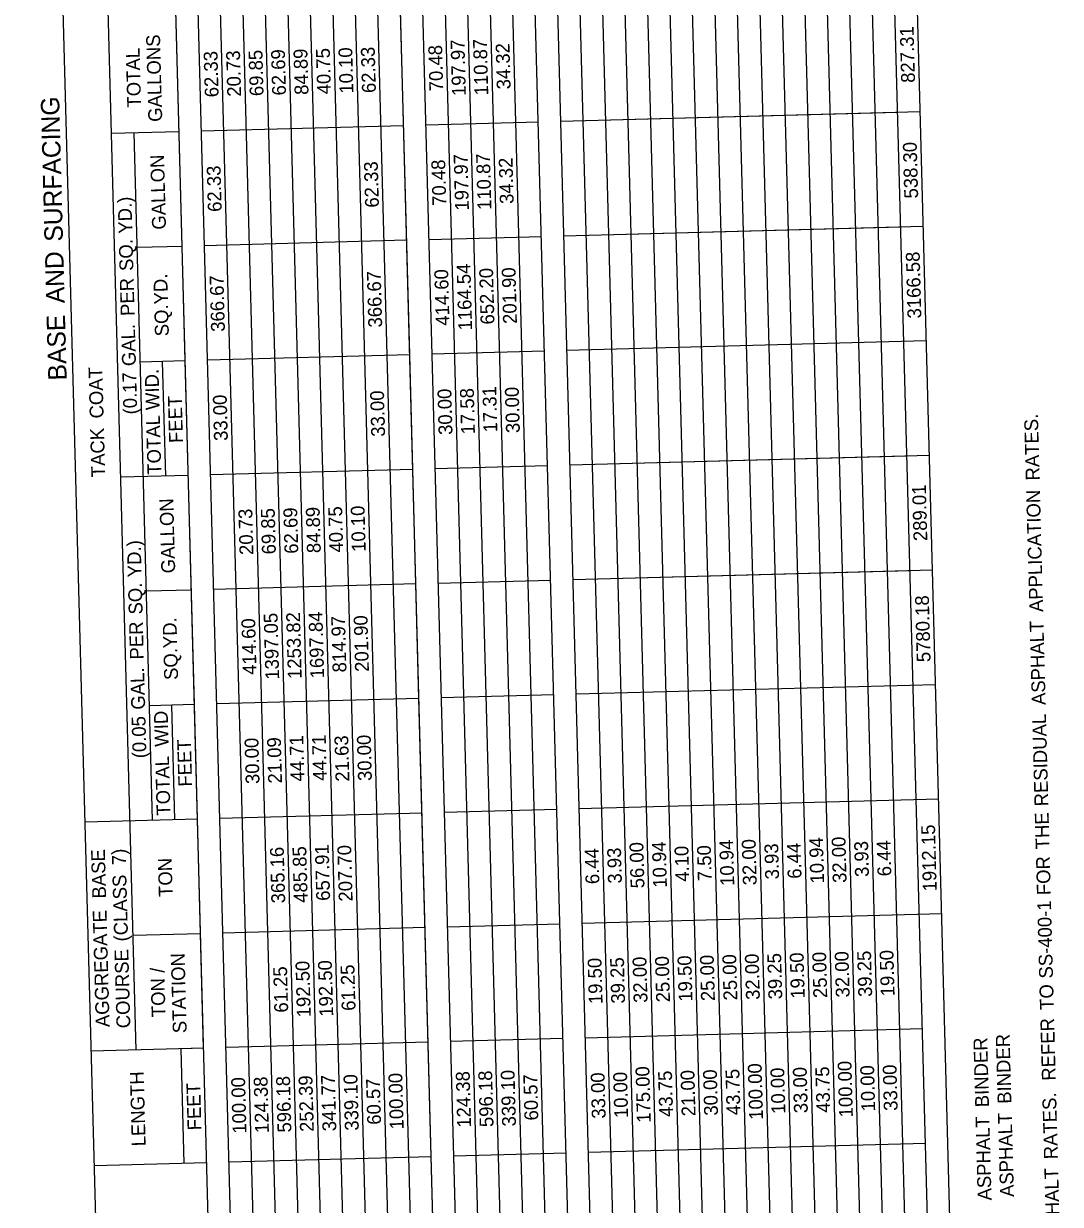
# Model space of a CAD drawing. Extents: x 1930093 to 1931323, y 596452 to 607874.
# Drawn here: x 1930485 to 1930935, y 604236 to 604748 of the extents above; entities that cross this region are included whole.
import ezdxf

# ---------------------------------------------------------------- set-up
doc = ezdxf.new("R2010")
doc.units = 0
doc.layers.add('Default', color=7, linetype='Continuous')

msp = doc.modelspace()

# ---------------------------------------------------------------- linework, layer by layer
at = {"layer": 'Default'}
for p, q in [((1930826.82, 603925.41), (1930787.13, 605403.95)), ((1930836.57, 603925.67), (1930796.88, 605404.22)), ((1930846.32, 603925.93), (1930806.63, 605404.48)), ((1930856.06, 603926.2), (1930816.37, 605404.74)), ((1930865.81, 603926.46), (1930826.12, 605405)), ((1930875.55, 603926.72), (1930835.86, 605405.26)), ((1930885.3, 603926.98), (1930845.61, 605405.52)), ((1930895.05, 603927.24), (1930855.36, 605405.79)), ((1930641.64, 603920.44), (1930601.95, 605398.98)), ((1930651.39, 603920.7), (1930611.7, 605399.24)), ((1930661.13, 603920.96), (1930621.44, 605399.51)), ((1930670.88, 603921.23), (1930631.19, 605399.77)), ((1930680.63, 603921.49), (1930640.93, 605400.03)), ((1930690.37, 603921.75), (1930650.68, 605400.29)), ((1930700.12, 603922.01), (1930660.43, 605400.55)), ((1930709.86, 603922.27), (1930670.17, 605400.81)), ((1930719.61, 603922.53), (1930679.92, 605401.08)), ((1930729.36, 603922.8), (1930689.67, 605401.34)), ((1930729.36, 603922.8), (1930689.67, 605401.34)), ((1930739.1, 603923.06), (1930699.41, 605401.6)), ((1930748.85, 603923.32), (1930709.16, 605401.86)), ((1930758.6, 603923.58), (1930718.91, 605402.12)), ((1930768.34, 603923.84), (1930728.65, 605402.38)), ((1930778.09, 603924.1), (1930738.4, 605402.65)), ((1930787.84, 603924.37), (1930748.15, 605402.91)), ((1930797.58, 603924.63), (1930757.89, 605403.17)), ((1930807.33, 603924.89), (1930767.64, 605403.43)), ((1930817.08, 603925.15), (1930777.39, 605403.69)), ((1930524.68, 603917.3), (1930484.99, 605395.84)), ((1930533.84, 604302.81), (1930504.48, 605396.37)), ((1930573.41, 603918.61), (1930533.72, 605397.15)), ((1930583.16, 603918.87), (1930543.47, 605397.41)), ((1930592.91, 603919.13), (1930553.22, 605397.67)), ((1930602.65, 603919.39), (1930562.96, 605397.94)), ((1930612.4, 603919.66), (1930572.71, 605398.2)), ((1930622.15, 603919.92), (1930582.46, 605398.46)), ((1930631.89, 603920.18), (1930592.2, 605398.72)), ((1930553.74, 604651.54), (1930549.74, 604800.67)), ((1930652.54, 604604.45), (1930648.53, 604753.58)), ((1930874.04, 604709.89), (1930718.09, 604705.7)), ((1930864.29, 604709.62), (1930718.09, 604705.7)), ((1930649.87, 604703.87), (1930562.15, 604701.51)), ((1930649.87, 604703.87), (1930562.15, 604701.51)), ((1930708.35, 604705.44), (1930659.62, 604704.13)), ((1930708.35, 604705.44), (1930659.62, 604704.13)), ((1930552.4, 604701.25), (1930523.16, 604700.47)), ((1930540.92, 604402.49), (1930532.91, 604700.73)), ((1930875.37, 604660.18), (1930719.43, 604655.99)), ((1930865.63, 604659.92), (1930719.43, 604655.99)), ((1930553.74, 604651.54), (1930534.25, 604651.02)), ((1930555.07, 604601.84), (1930553.74, 604651.54)), ((1930651.2, 604654.16), (1930563.49, 604651.81)), ((1930651.2, 604654.16), (1930563.49, 604651.81)), ((1930709.68, 604655.73), (1930660.95, 604654.42)), ((1930709.68, 604655.73), (1930660.95, 604654.42)), ((1930876.71, 604610.47), (1930720.76, 604606.29)), ((1930876.71, 604610.47), (1930720.76, 604606.29)), ((1930711.02, 604606.02), (1930662.28, 604604.72)), ((1930711.02, 604606.02), (1930662.28, 604604.72)), ((1930555.07, 604601.84), (1930535.58, 604601.31)), ((1930555.07, 604601.84), (1930545.33, 604601.58)), ((1930546.66, 604551.87), (1930545.33, 604601.58)), ((1930559.08, 604452.72), (1930555.07, 604601.84)), ((1930652.54, 604604.45), (1930564.82, 604602.1)), ((1930652.54, 604604.45), (1930564.82, 604602.1)), ((1930653.87, 604554.75), (1930652.54, 604604.45)), ((1930878.04, 604560.76), (1930722.1, 604556.58)), ((1930868.3, 604560.5), (1930722.1, 604556.58)), ((1930653.87, 604554.75), (1930566.15, 604552.39)), ((1930653.87, 604554.75), (1930566.15, 604552.39)), ((1930656.54, 604455.33), (1930653.87, 604554.75)), ((1930712.35, 604556.32), (1930663.62, 604555.01)), ((1930712.35, 604556.32), (1930663.62, 604555.01)), ((1930556.41, 604552.13), (1930527.17, 604551.35)), ((1930879.38, 604511.06), (1930723.43, 604506.87)), ((1930869.63, 604510.8), (1930723.43, 604506.87)), ((1930557.74, 604502.42), (1930538.25, 604501.9)), ((1930655.21, 604505.04), (1930567.49, 604502.69)), ((1930655.21, 604505.04), (1930567.49, 604502.69)), ((1930713.69, 604506.61), (1930664.95, 604505.3)), ((1930713.69, 604506.61), (1930664.95, 604505.3)), ((1930880.71, 604461.35), (1930724.77, 604457.16)), ((1930880.71, 604461.35), (1930724.77, 604457.16)), ((1930715.02, 604456.9), (1930666.29, 604455.59)), ((1930715.02, 604456.9), (1930666.29, 604455.59)), ((1930559.08, 604452.72), (1930539.58, 604452.19)), ((1930559.08, 604452.72), (1930549.33, 604452.45)), ((1930550.66, 604402.75), (1930549.33, 604452.45)), ((1930563.08, 604303.6), (1930559.08, 604452.72)), ((1930656.54, 604455.33), (1930568.82, 604452.98)), ((1930656.54, 604455.33), (1930568.82, 604452.98)), ((1930670.88, 603921.23), (1930656.54, 604455.33)), ((1930882.04, 604411.64), (1930726.1, 604407.46)), ((1930882.04, 604411.64), (1930726.1, 604407.46)), ((1930657.88, 604405.63), (1930570.16, 604403.27)), ((1930657.88, 604405.63), (1930570.16, 604403.27)), ((1930716.35, 604407.2), (1930667.62, 604405.89)), ((1930716.35, 604407.2), (1930667.62, 604405.89)), ((1930560.41, 604403.01), (1930511.68, 604401.7)), ((1930883.38, 604361.94), (1930727.44, 604357.75)), ((1930883.38, 604361.94), (1930727.44, 604357.75)), ((1930659.21, 604355.92), (1930571.49, 604353.56)), ((1930659.21, 604355.92), (1930571.49, 604353.56)), ((1930717.69, 604357.49), (1930668.96, 604356.18)), ((1930717.69, 604357.49), (1930668.96, 604356.18)), ((1930561.74, 604353.3), (1930532.51, 604352.52)), ((1930719.02, 604307.78), (1930670.29, 604306.47)), ((1930719.02, 604307.78), (1930670.29, 604306.47)), ((1930874.97, 604311.97), (1930728.77, 604308.04)), ((1930874.97, 604311.97), (1930728.77, 604308.04)), ((1930563.08, 604303.6), (1930514.35, 604302.29)), ((1930563.08, 604303.6), (1930553.33, 604303.33)), ((1930554.67, 604253.63), (1930553.33, 604303.33)), ((1930660.54, 604306.21), (1930572.83, 604303.86)), ((1930660.54, 604306.21), (1930572.83, 604303.86)), ((1930876.3, 604262.26), (1930730.1, 604258.34)), ((1930876.3, 604262.26), (1930730.1, 604258.34)), ((1930661.88, 604256.5), (1930574.16, 604254.15)), ((1930661.88, 604256.5), (1930574.16, 604254.15)), ((1930720.36, 604258.07), (1930671.62, 604256.77)), ((1930720.36, 604258.07), (1930671.62, 604256.77)), ((1930677.96, 604020.9), (1930671.62, 604256.77)), ((1930564.41, 604253.89), (1930515.68, 604252.58))]:
    msp.add_line(p, q, dxfattribs=at)

# ---------------------------------------------------------------- texts
for s, height, p in [('GALLONS', 6, (1930545.16, 604705.63)), ('827.31', 6, (1930871.82, 604722.56)), ('70.48', 6, (1930667.1, 604718.9)), ('197.97', 6, (1930676.91, 604716.84)), ('110.87', 6, (1930686.65, 604717.1)), ('34.32', 6, (1930696.34, 604719.72)), ('TOTAL', 6, (1930535.99, 604711.83)), ('62.33', 6, (1930569.63, 604716.29)), ('20.73', 6, (1930579.38, 604716.55)), ('69.85', 6, (1930589.13, 604716.79)), ('62.69', 6, (1930598.87, 604717.07)), ('84.89', 6, (1930608.62, 604717.33)), ('40.75', 6, (1930618.37, 604717.57)), ('10.10', 6, (1930628.11, 604717.87)), ('62.33', 6, (1930637.86, 604718.12)), (' SURFACING', 8, (1930502.17, 604650.7)), ('538.30', 6, (1930873.17, 604672.38)), ('GALLON', 6, (1930546.79, 604658.86)), ('62.33', 6, (1930639.19, 604668.41)), ('70.48', 6, (1930668.43, 604669.19)), ('197.97', 6, (1930678.24, 604667.13)), ('110.87', 6, (1930687.99, 604667.39)), ('34.32', 6, (1930697.67, 604670.01)), ('62.33', 6, (1930570.97, 604666.58)), (' YD.)', 6, (1930532.27, 604654.89)), (' SQ.', 6, (1930532.7, 604638.7)), (' AND', 8, (1930502.89, 604623.94)), ('3166.58', 6, (1930874.57, 604620.32)), ('414.60', 6, (1930669.83, 604617.17)), ('1164.54', 6, (1930679.64, 604615.11)), ('652.20', 6, (1930689.32, 604617.7)), ('201.90', 6, (1930699.07, 604617.96)), (' PER', 6, (1930533.22, 604619.18)), ('SQ.YD.', 6, (1930548.03, 604612.59)), ('366.67', 6, (1930572.36, 604614.54)), ('366.67', 6, (1930640.59, 604616.38)), ('BASE', 8, (1930503.7, 604593.44)), (' GAL.', 6, (1930533.81, 604597.41)), (' COAT', 6, (1930519.79, 604574.7)), ('(0.17', 6, (1930534.31, 604578.69)), ('TOTAL WID.', 6, (1930544.77, 604552.52)), ('30.00', 6, (1930671.1, 604569.79)), ('17.58', 6, (1930680.85, 604570.04)), ('17.31', 6, (1930690.58, 604570.89)), ('30.00', 6, (1930700.34, 604570.58)), ('FEET', 6, (1930554.15, 604566.31)), ('33.00', 6, (1930573.63, 604567.18)), ('33.00', 6, (1930641.86, 604569.01)), (' RATES.', 6, (1930925.96, 604547.77)), ('TACK', 6, (1930520.41, 604551.44)), ('289.01', 6, (1930877.16, 604523.73)), (' APPLICATION', 6, (1930927.49, 604490.71)), ('GALLON', 6, (1930550.79, 604509.74)), ('84.89', 6, (1930613.96, 604518.5)), ('40.75', 6, (1930623.7, 604518.75)), ('10.10', 6, (1930633.45, 604519.04)), ('20.73', 6, (1930584.72, 604517.72)), ('69.85', 6, (1930594.46, 604517.96)), ('62.69', 6, (1930604.21, 604518.24)), (' YD.)', 6, (1930536.27, 604505.83)), (' SQ.', 6, (1930536.7, 604489.64)), ('5780.18', 6, (1930878.57, 604471.2)), ('1397.05', 6, (1930595.92, 604463.59)), ('1253.82', 6, (1930605.67, 604463.91)), ('1697.84', 6, (1930615.41, 604464.15)), (' PER', 6, (1930537.23, 604470.12)), ('SQ.YD.', 6, (1930552.03, 604463.47)), ('414.60', 6, (1930586.11, 604465.7)), ('814.97', 6, (1930625.1, 604466.73)), ('201.90', 6, (1930634.85, 604467)), (' ASPHALT', 6, (1930928.57, 604450.36)), (' GAL.', 6, (1930537.81, 604448.35)), ('(0.05', 6, (1930538.32, 604429.51)), (' WID', 6, (1930548, 604432.29)), (' RESIDUAL', 6, (1930929.75, 604406.41)), ('FEET', 6, (1930558.15, 604417.19)), ('30.00', 6, (1930587.38, 604418.32)), ('21.09', 6, (1930597.13, 604418.56)), ('44.71', 6, (1930606.86, 604419.41)), ('44.71', 6, (1930616.61, 604419.67)), ('21.63', 6, (1930626.37, 604419.35)), ('30.00', 6, (1930636.12, 604419.63)), ('TOTAL', 6, (1930548.74, 604404.61)), (' THE', 6, (1930930.25, 604387.77)), ('1912.15', 6, (1930881.24, 604371.73)), ('10.94', 6, (1930832.38, 604375.15)), ('32.00', 6, (1930842.13, 604375.41)), (' BASE', 6, (1930520.88, 604366.42)), (' 7)', 6, (1930529.49, 604380.9)), ('365.16', 6, (1930598.53, 604366.53)), ('485.85', 6, (1930608.28, 604366.77)), ('657.91', 6, (1930618.01, 604367.64)), ('207.70', 6, (1930627.77, 604367.33)), ('6.44', 6, (1930734.85, 604374.87)), ('3.93', 6, (1930744.6, 604375.12)), ('56.00', 6, (1930754.41, 604373.06)), ('10.94', 6, (1930764.16, 604373.32)), ('4.10', 6, (1930773.84, 604375.91)), ('7.50', 6, (1930783.59, 604376.17)), ('10.94', 6, (1930793.39, 604374.11)), ('32.00', 6, (1930803.14, 604374.37)), ('3.93', 6, (1930812.83, 604376.95)), ('6.44', 6, (1930822.57, 604377.22)), ('3.93', 6, (1930851.81, 604377.99)), ('6.44', 6, (1930861.56, 604378.27)), ('TON', 6, (1930549.69, 604369.33)), (' FOR', 6, (1930930.79, 604367.87)), (' (CLASS', 6, (1930530.38, 604347.79)), (' SS-400-1', 6, (1930931.76, 604331.69)), ('AGGREGATE', 6, (1930522.32, 604312.82)), ('COURSE', 6, (1930531.33, 604312.35)), ('STATION', 6, (1930555.77, 604310.2)), ('19.50', 6, (1930775.24, 604323.88)), ('25.00', 6, (1930784.98, 604324.14)), ('25.00', 6, (1930794.73, 604324.4)), ('32.00', 6, (1930804.48, 604324.66)), ('39.25', 6, (1930814.22, 604324.89)), ('19.50', 6, (1930823.97, 604325.18)), ('25.00', 6, (1930833.72, 604325.45)), ('32.00', 6, (1930843.46, 604325.71)), ('39.25', 6, (1930853.21, 604325.93)), ('19.50', 6, (1930862.95, 604326.23)), (' /', 6, (1930546.13, 604334.19)), ('61.25', 6, (1930599.8, 604319.13)), ('192.50', 6, (1930609.61, 604317.1)), ('192.50', 6, (1930619.36, 604317.36)), ('61.25', 6, (1930629.04, 604319.92)), ('19.50', 6, (1930736.25, 604322.83)), ('39.25', 6, (1930746, 604323.06)), ('32.00', 6, (1930755.74, 604323.35)), ('25.00', 6, (1930765.49, 604323.61)), ('TON', 6, (1930546.58, 604317.17)), (' TO', 6, (1930932.12, 604318.1)), ('  REFER', 6, (1930933.01, 604285.15)), (' BINDER', 6, (1930904, 604275.84)), (' BINDER', 6, (1930913.71, 604277.36)), ('100.00', 6, (1930844.86, 604273.67)), ('LENGTH', 6, (1930537.96, 604261.13)), ('100.00', 6, (1930649.93, 604268.44)), ('124.38', 6, (1930679.17, 604269.21)), ('596.18', 6, (1930688.92, 604269.47)), ('339.10', 6, (1930698.66, 604269.75)), ('33.00', 6, (1930737.58, 604273.12)), ('10.00', 6, (1930747.33, 604273.38)), ('175.00', 6, (1930757.14, 604271.32)), ('43.75', 6, (1930766.83, 604273.87)), ('21.00', 6, (1930776.57, 604274.17)), ('30.00', 6, (1930786.32, 604274.43)), ('43.75', 6, (1930796.06, 604274.66)), ('100.00', 6, (1930805.87, 604272.62)), ('10.00', 6, (1930815.56, 604275.21)), ('33.00', 6, (1930825.3, 604275.48)), ('43.75', 6, (1930835.05, 604275.7)), ('10.00', 6, (1930854.54, 604276.26)), ('33.00', 6, (1930864.29, 604276.52)), ('FEET', 6, (1930562.16, 604268.07)), ('100.00', 6, (1930581.7, 604266.61)), ('124.38', 6, (1930591.45, 604266.85)), ('596.18', 6, (1930601.2, 604267.11)), ('252.39', 6, (1930610.94, 604267.38)), ('341.77', 6, (1930620.69, 604267.64)), ('339.10', 6, (1930630.44, 604267.91)), ('60.57', 6, (1930640.12, 604270.49)), ('60.57', 6, (1930708.35, 604272.33)), (' RATES.', 6, (1930933.86, 604253.28)), ('  ASPHALT', 6, (1930905.14, 604233.16)), ('  ASPHALT', 6, (1930914.86, 604234.68)), (' ASPHALT', 6, (1930934.95, 604212.93))]:
    msp.add_text(s, height=height, rotation=91.5377, dxfattribs=at).set_placement(p)

doc.saveas('drawing.dxf')
